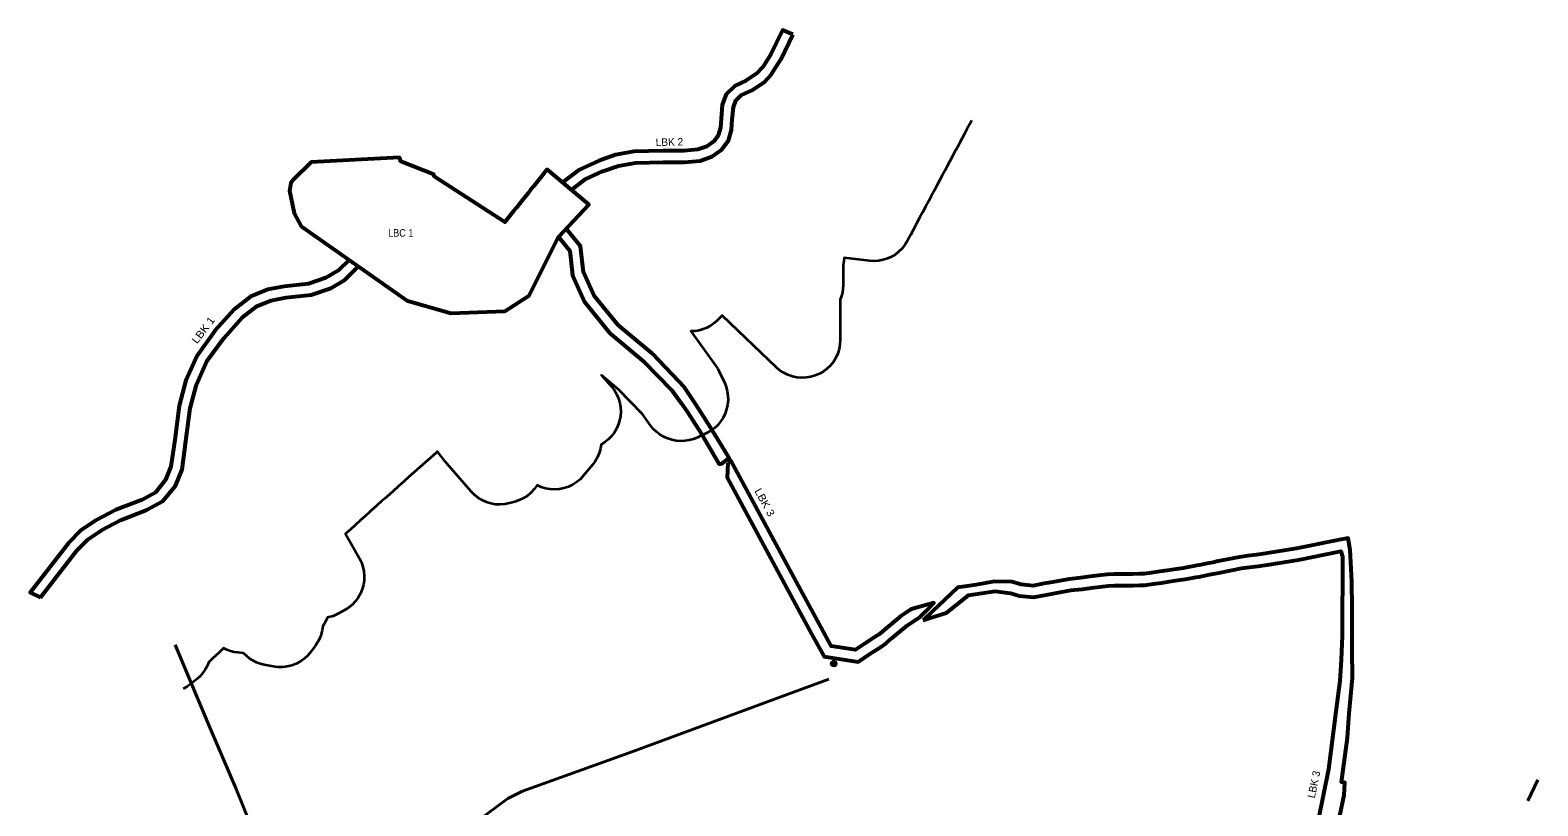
# Model space of a CAD drawing. Extents: x -555426 to -553015, y -1186745 to -1182687.
# Drawn here: x -555288 to -553293, y -1183714 to -1182687 of the extents above; entities that cross this region are included whole.
import ezdxf
from ezdxf.enums import TextEntityAlignment as Align

# ---------------------------------------------------------------- set-up
doc = ezdxf.new("R2010")
doc.units = 0
doc.header["$LTSCALE"] = 4
for name, color, linetype, lineweight in [('12', 7, 'Continuous', 53), ('14', 7, 'Continuous', 53), ('50', 7, 'Continuous', 35), ('51', 7, 'Continuous', 40), ('7', 7, 'Continuous', 35)]:
    doc.layers.add(name, color=color, linetype=linetype, lineweight=lineweight)
doc.layers.add('13', color=7, linetype='Continuous')

msp = doc.modelspace()

# ---------------------------------------------------------------- hatches: boundary and pattern name
at = {"layer": '50'}
msp.add_hatch(color=256, dxfattribs=at).paths.add_polyline_path([(-554222.657, -1183525.485, 1), (-554226.956, -1183525.485, 1)])

# ---------------------------------------------------------------- linework, layer by layer
at = {"layer": '12'}
for points in [[(-554278.839, -1182692.52), (-554292.751, -1182686.823), (-554308.218, -1182718.407), (-554319.193, -1182736.187), (-554326.623, -1182744.22), (-554340.883, -1182753.585), (-554355.867, -1182760.594), (-554367.234, -1182771.676), (-554372.315, -1182785.509), (-554374.031, -1182803.892), (-554374.904, -1182816.334), (-554377.789, -1182826.145), (-554383.471, -1182834.21), (-554392.863, -1182840.727), (-554404.898, -1182844.939), (-554423.272, -1182846.668), (-554450.709, -1182846.668), (-554488.789, -1182847.373), (-554513.544, -1182851.742), (-554535.945, -1182859.69), (-554561.973, -1182871.74), (-554583.662, -1182888.49)], [(-554571.889, -1182898.351), (-554554.141, -1182884.644), (-554530.273, -1182873.594), (-554509.706, -1182866.296), (-554487.337, -1182862.349), (-554450.571, -1182861.668), (-554422.568, -1182861.668), (-554401.67, -1182859.701), (-554385.985, -1182854.211), (-554372.739, -1182845.02), (-554364.099, -1182832.757), (-554360.054, -1182819.006), (-554359.079, -1182805.114), (-554357.561, -1182788.847), (-554354.326, -1182780.042), (-554347.213, -1182773.106), (-554333.551, -1182766.715), (-554316.857, -1182755.752), (-554307.193, -1182745.305), (-554295.068, -1182725.663), (-554278.839, -1182692.52)], [(-554373.37, -1183261.05), (-554363.18, -1183253.13), (-554387.431, -1183213.215), (-554406.75, -1183182.832), (-554421.72, -1183160.34), (-554465.312, -1183114.688), (-554510.264, -1183077.441), (-554542.023, -1183038.398), (-554556.094, -1183007.245), (-554559.906, -1182972.999), (-554577.646, -1182951.011)], [(-554589.32, -1182960.43), (-554574.33, -1182979.01), (-554570.74, -1183011.26), (-554554.89, -1183046.35), (-554520.97, -1183088.05), (-554475.52, -1183125.71), (-554439.49, -1183162.97), (-554426.66, -1183180.83), (-554419.18, -1183191.24), (-554400.25, -1183221.01), (-554377.12, -1183260.83), (-554373.37, -1183261.05)], [(-554866.158, -1182990.719), (-554881.217, -1183005.495), (-554896.861, -1183014.795), (-554919.81, -1183022.589), (-554952.084, -1183025.999), (-554973.942, -1183030.127), (-554996.146, -1183039.358), (-555018.025, -1183056.321), (-555043.915, -1183085.06), (-555067.478, -1183117.431), (-555082.368, -1183150.814), (-555091.194, -1183184.207), (-555097.029, -1183229.007), (-555101.98, -1183264.569), (-555109.072, -1183282.298), (-555122.428, -1183298.735), (-555140.345, -1183308.431), (-555175.164, -1183322.037), (-555200.858, -1183335.359), (-555221.24, -1183349.19), (-555237.778, -1183365.971), (-555288.383, -1183431.18), (-555274.545, -1183437.814)], [(-555274.545, -1183437.814), (-555226.472, -1183375.869), (-555211.594, -1183360.772), (-555193.168, -1183348.269), (-555168.964, -1183335.719), (-555134.021, -1183322.065), (-555112.666, -1183310.509), (-555095.992, -1183289.986), (-555087.376, -1183268.445), (-555082.163, -1183231.011), (-555076.444, -1183187.105), (-555068.176, -1183155.818), (-555054.422, -1183124.983), (-555032.247, -1183094.52), (-555007.777, -1183067.355), (-554988.538, -1183052.44), (-554969.624, -1183044.577), (-554949.9, -1183040.851), (-554916.57, -1183037.331), (-554890.547, -1183028.493), (-554872.001, -1183017.465), (-554853.67, -1182999.481)], [(-554110.58, -1183463.31), (-554103.48, -1183456.27), (-554092.27, -1183445.06), (-554122.231, -1183453.201), (-554124.207, -1183454.614), (-554136.184, -1183462.634), (-554157.583, -1183480.555), (-554164.408, -1183486.48), (-554171.218, -1183490.925), (-554184.025, -1183499.312), (-554196.042, -1183507.394), (-554228.053, -1183502.414), (-554240.95, -1183478.721), (-554274.264, -1183417.699), (-554310.485, -1183350.454), (-554361.077, -1183256.605), (-554365.04, -1183259.86)], [(-554365.04, -1183259.86), (-554366.04, -1183279.01), (-554323.69, -1183357.57), (-554287.45, -1183424.85), (-554254.12, -1183485.9), (-554237.684, -1183516.096), (-554192.544, -1183523.119), (-554175.73, -1183511.81), (-554163.01, -1183503.48), (-554155.35, -1183498.48), (-554147.85, -1183491.97), (-554127.17, -1183474.65), (-554115.67, -1183466.95), (-554110.58, -1183463.31)], [(-553560.8, -1183754.18), (-553549.47, -1183699.63), (-553548.22, -1183682.87), (-553552.596, -1183682.503), (-553545.043, -1183623.517), (-553542.638, -1183591.193), (-553538.153, -1183544.346), (-553538.853, -1183507.002), (-553538.59, -1183491.209), (-553538.57, -1183472.914), (-553538.638, -1183452.234), (-553539.179, -1183416.532), (-553541.455, -1183374.786), (-553543.938, -1183359.474), (-553557.65, -1183362.2), (-553612.39, -1183373.1), (-553653.56, -1183379.74), (-553665.24, -1183381.36), (-553676.67, -1183382.9), (-553687.79, -1183384.46), (-553718.16, -1183390.43), (-553722.99, -1183391.53), (-553728.14, -1183392.45), (-553732.81, -1183393.34), (-553738.51, -1183394.57), (-553744.23, -1183395.71), (-553748.21, -1183396.36), (-553752.95, -1183397.28), (-553757.56, -1183398.09), (-553762.06, -1183398.94), (-553771.65, -1183400.34), (-553782.96, -1183402.01), (-553793.28, -1183403.54), (-553804.29, -1183405.2), (-553814.16, -1183406.62), (-553820.26, -1183406.69), (-553829.02, -1183406.87), (-553837.21, -1183407), (-553845.49, -1183407.06), (-553853.98, -1183407.2), (-553862.46, -1183407.33), (-553870.96, -1183408.4), (-553885.46, -1183410.23), (-553897.94, -1183411.82), (-553913.31, -1183413.52), (-553934.77, -1183417.42), (-553946.22, -1183419.56), (-553961.04, -1183422.25), (-553976.68, -1183420.7), (-553988.73, -1183417.33), (-554011.96, -1183416.74), (-554036.25, -1183421.25), (-554048.21, -1183422.95), (-554061.25, -1183424.79), (-554078.44, -1183441.14), (-554094.02, -1183455.82), (-554106.58, -1183467.73)], [(-554106.58, -1183467.73), (-554075.726, -1183458.421), (-554046.426, -1183434.944), (-554011.182, -1183429.704), (-553990.975, -1183432.278), (-553979.461, -1183435.498), (-553960.428, -1183437.384), (-553943.503, -1183434.312), (-553932.051, -1183432.172), (-553911.142, -1183428.372), (-553896.168, -1183426.715), (-553883.573, -1183425.111), (-553869.084, -1183423.282), (-553861.405, -1183422.316), (-553853.741, -1183422.198), (-553845.312, -1183422.059), (-553837.037, -1183421.999), (-553828.747, -1183421.868), (-553820.02, -1183421.688), (-553813.001, -1183421.608), (-553802.104, -1183420.04), (-553791.062, -1183418.375), (-553780.765, -1183416.848), (-553769.471, -1183415.181), (-553759.583, -1183413.737), (-553754.87, -1183412.847), (-553750.223, -1183412.031), (-553745.572, -1183411.128), (-553741.554, -1183410.472), (-553735.462, -1183409.258), (-553729.823, -1183408.041), (-553725.417, -1183407.201), (-553720.004, -1183406.234), (-553715.047, -1183405.105), (-553685.3, -1183399.258), (-553674.627, -1183397.76), (-553663.208, -1183396.222), (-553651.335, -1183394.575), (-553609.73, -1183387.865), (-553553.598, -1183376.687), (-553551.63, -1183383.72), (-553552.01, -1183488.29), (-553553.42, -1183520.28), (-553554.96, -1183548.08), (-553560.51, -1183589.02), (-553570.03, -1183665.12), (-553583.88, -1183732.87)]]:
    msp.add_lwpolyline(points, dxfattribs=at)
at = {"layer": '14'}
msp.add_lwpolyline([(-554929.743, -1182946.105), (-554788.831, -1183044.975), (-554731.543, -1183061.607), (-554659.932, -1183058.835), (-554628.053, -1183038.044), (-554591, -1182963.93), (-554589.32, -1182960.43), (-554548.935, -1182917.576), (-554604.33, -1182871.18), (-554607.57, -1182875.37), (-554611.33, -1182880.08), (-554615.1, -1182884.8), (-554618.76, -1182889.39), (-554622.34, -1182893.87), (-554625.97, -1182898.29), (-554629.38, -1182902.63), (-554633.35, -1182907.44), (-554637.08, -1182912.33), (-554640.7, -1182916.69), (-554644.85, -1182921.99), (-554648.51, -1182926.36), (-554652.29, -1182931.05), (-554660.11, -1182940.98), (-554753.5, -1182880.52), (-554754.24, -1182878), (-554797.61, -1182860.51), (-554799.43, -1182855.5), (-554916.24, -1182861.73), (-554940.94, -1182885.43), (-554943.35, -1182888.88), (-554945.315, -1182899.449), (-554938.752, -1182929.243)], close=True, dxfattribs=at)
at = {"layer": '50'}
for radius in [3.332, 2.149]:
    msp.add_circle((-554224.806, -1183525.485), radius, dxfattribs=at)
at = {"layer": '51'}
msp.add_line((-553306.223, -1183706.964), (-553292.941, -1183679.475), dxfattribs=at)
for points in [[(-555096.259, -1183500.696), (-555050.637, -1183609.844), (-555016.334, -1183690.35), (-554989.423, -1183757.11), (-554981.106, -1183783.327), (-554976.024, -1183820.635), (-554968.516, -1183877.229), (-554966.438, -1183902.87), (-554901.757, -1183903.794), (-554892.286, -1183893.629), (-554839.155, -1183856.09), (-554793.88, -1183825.366), (-554760.962, -1183788.058), (-554748.083, -1183774.083)], [(-554722.904, -1183753.292), (-554656.144, -1183703.857), (-554636.97, -1183694.155), (-554490.514, -1183641.718), (-554303.17, -1183572.417), (-554231.271, -1183546.197)]]:
    msp.add_lwpolyline(points, dxfattribs=at)
at = {"layer": '7'}
for points in [[(-554042.529, -1182806.54), (-554045.307, -1182811.751), (-554048.608, -1182817.945), (-554051.847, -1182824.042), (-554055.031, -1182830.019), (-554058.369, -1182836.284), (-554061.654, -1182842.455), (-554064.862, -1182848.47), (-554068.062, -1182854.47), (-554071.245, -1182860.438), (-554074.618, -1182866.785), (-554077.993, -1182873.121), (-554081.352, -1182879.409), (-554084.784, -1182885.856), (-554088.415, -1182892.678), (-554092.103, -1182899.602), (-554095.816, -1182906.568), (-554099.521, -1182913.521), (-554103.242, -1182920.521), (-554107.3, -1182928.135), (-554111.209, -1182935.464), (-554115.164, -1182942.885), (-554119.262, -1182950.592), (-554123.347, -1182958.259), (-554127.513, -1182966.07), (-554130.633, -1182971.163), (-554134.339, -1182975.847), (-554138.576, -1182980.056), (-554143.285, -1182983.73), (-554148.399, -1182986.816), (-554153.844, -1182989.27), (-554159.543, -1182991.058), (-554165.415, -1182992.153), (-554171.375, -1182992.54), (-554177.339, -1182992.214), (-554211.103, -1182988.333), (-554211.616, -1182992.362), (-554212.217, -1182998.363), (-554212.212, -1183005.39), (-554212.332, -1183015.038), (-554212.381, -1183024.344), (-554212.63, -1183029.193), (-554213.38, -1183033.99), (-554214.624, -1183038.683), (-554216.347, -1183043.222)], [(-554216.347, -1183043.222), (-554216.32, -1183061.355), (-554216.18, -1183097.022), (-554216.546, -1183103.155), (-554217.66, -1183109.197), (-554219.508, -1183115.057), (-554222.06, -1183120.645), (-554225.278, -1183125.879), (-554229.114, -1183130.678), (-554233.51, -1183134.971), (-554238.398, -1183138.692), (-554243.707, -1183141.785), (-554249.354, -1183144.204), (-554255.256, -1183145.913), (-554261.323, -1183146.884), (-554267.462, -1183147.104), (-554273.583, -1183146.569), (-554279.592, -1183145.288), (-554285.398, -1183143.28), (-554290.914, -1183140.574), (-554296.057, -1183137.213), (-554300.748, -1183133.246), (-554351.34, -1183084.834), (-554372.353, -1183064.723), (-554379.064, -1183071.27), (-554383.237, -1183074.913), (-554387.788, -1183078.071), (-554392.66, -1183080.706), (-554397.795, -1183082.785), (-554403.128, -1183084.283), (-554408.594, -1183085.181), (-554414.126, -1183085.468), (-554381.247, -1183130.982), (-554378.419, -1183135.341), (-554376.643, -1183138.705), (-554369.573, -1183153.435), (-554367.294, -1183159.027), (-554365.705, -1183164.854), (-554364.83, -1183170.829), (-554364.682, -1183176.866), (-554365.263, -1183182.877), (-554366.565, -1183188.774), (-554368.567, -1183194.471), (-554371.242, -1183199.885), (-554374.551, -1183204.938), (-554378.444, -1183209.554), (-554382.865, -1183213.668), (-554387.75, -1183217.218), (-554393.028, -1183220.154), (-554405.038, -1183225.914), (-554410.413, -1183228.117), (-554416.008, -1183229.683), (-554421.746, -1183230.588), (-554427.551, -1183230.822), (-554433.343, -1183230.382), (-554439.046, -1183229.272), (-554444.581, -1183227.508), (-554449.874, -1183225.115), (-554454.854, -1183222.123), (-554459.454, -1183218.574), (-554463.61, -1183214.515), (-554467.268, -1183210.002), (-554477.97, -1183195.105), (-554509.545, -1183162.451), (-554532.143, -1183143.633), (-554518.631, -1183159.243), (-554515.073, -1183163.964), (-554512.097, -1183169.072), (-554509.748, -1183174.496), (-554508.056, -1183180.16), (-554507.046, -1183185.985), (-554506.733, -1183191.888), (-554507.12, -1183197.787), (-554508.203, -1183203.599), (-554509.965, -1183209.241), (-554512.382, -1183214.636), (-554515.421, -1183219.707), (-554519.039, -1183224.382), (-554523.184, -1183228.597), (-554527.799, -1183232.292), (-554532.818, -1183235.414), (-554533.691, -1183241.174), (-554535.262, -1183246.784), (-554537.506, -1183252.16), (-554540.391, -1183257.221), (-554543.872, -1183261.892), (-554556.435, -1183277.021), (-554560.631, -1183281.483), (-554565.344, -1183285.395), (-554570.503, -1183288.696), (-554576.03, -1183291.337), (-554581.839, -1183293.277), (-554587.844, -1183294.487), (-554593.952, -1183294.947), (-554600.07, -1183294.652), (-554606.105, -1183293.606), (-554611.965, -1183291.825), (-554617.561, -1183289.335), (-554621.144, -1183294.456), (-554625.349, -1183299.079), (-554630.108, -1183303.13)], [(-554630.108, -1183303.13), (-554635.344, -1183306.542), (-554640.971, -1183309.26), (-554646.899, -1183311.241), (-554654.029, -1183313.161), (-554660.118, -1183314.4), (-554666.314, -1183314.875), (-554672.522, -1183314.578), (-554678.644, -1183313.513), (-554684.587, -1183311.697), (-554690.259, -1183309.157), (-554695.571, -1183305.934), (-554700.443, -1183302.077), (-554704.799, -1183297.644), (-554736.939, -1183260.594), (-554739.184, -1183257.811), (-554749.11, -1183244.563), (-554751.224, -1183246.463), (-554758.608, -1183253.016), (-554765.643, -1183259.215), (-554772.609, -1183265.479), (-554779.925, -1183272.041), (-554787.13, -1183278.372), (-554794.075, -1183284.625), (-554801.254, -1183291.06), (-554808.527, -1183297.581), (-554815.988, -1183304.186), (-554819.57, -1183307.298), (-554822.737, -1183310.117), (-554829.881, -1183316.589), (-554836.845, -1183322.79), (-554840.492, -1183326.144), (-554843.546, -1183328.959), (-554844.409, -1183329.736), (-554851.577, -1183336.044), (-554858.225, -1183341.946), (-554864.933, -1183348.163), (-554866.091, -1183349.204), (-554871.107, -1183353.57), (-554862.775, -1183368.352), (-554852.707, -1183386.106), (-554850.05, -1183391.53), (-554848.067, -1183397.236), (-554846.786, -1183403.138), (-554846.226, -1183409.153), (-554846.396, -1183415.19), (-554847.292, -1183421.164), (-554848.902, -1183426.985), (-554851.203, -1183432.57), (-554854.16, -1183437.837), (-554857.731, -1183442.709), (-554861.863, -1183447.114), (-554866.496, -1183450.989), (-554871.563, -1183454.277), (-554880.337, -1183459.153), (-554887.509, -1183462.425), (-554895.013, -1183464.436), (-554898.639, -1183472.211), (-554901.2, -1183475.868), (-554901.87, -1183481.339), (-554903.17, -1183486.695), (-554905.081, -1183491.865), (-554907.578, -1183496.778), (-554910.628, -1183501.369), (-554916.958, -1183509.929), (-554920.999, -1183514.731), (-554925.61, -1183518.989), (-554930.718, -1183522.636), (-554936.242, -1183525.615), (-554942.097, -1183527.877), (-554948.188, -1183529.389), (-554954.421, -1183530.125), (-554960.697, -1183530.075), (-554966.918, -1183529.239), (-554978.778, -1183526.879), (-554983.909, -1183525.59), (-554988.87, -1183523.75), (-554993.602, -1183521.383), (-554998.048, -1183518.516), (-555002.157, -1183515.183), (-555005.879, -1183511.423), (-555013.388, -1183510.752), (-555018.322, -1183510.063), (-555023.166, -1183508.9), (-555027.875, -1183507.273), (-555032.404, -1183505.197), (-555035.924, -1183508.403), (-555039.218, -1183511.498), (-555046.403, -1183518.17), (-555051.906, -1183523.608), (-555053.963, -1183528.636), (-555056.562, -1183533.406), (-555059.672, -1183537.861), (-555063.255, -1183541.945), (-555067.266, -1183545.609), (-555076.09, -1183552.726), (-555081.111, -1183556.284), (-555085.651, -1183558.726)]]:
    msp.add_lwpolyline(points, dxfattribs=at)

# ---------------------------------------------------------------- texts
at = {"layer": '13'}
for s, rotation, p in [('LBK 2', 1.489, (-554442.159, -1182839.876)), ('LBK 3', 78.305, (-553584.489, -1183686.383))]:
    msp.add_text(s, height=10, rotation=rotation, dxfattribs=at).set_placement(p, align=Align.CENTER)
at = {"layer": '13', "width": 0.9}
msp.add_text('LBC 1', height=10, dxfattribs=at).set_placement((-554797.917, -1182960.276), align=Align.CENTER)
at = {"layer": '13', "width": 1.1}
for s, rotation, p in [('LBK 1', 52.768, (-555055.332, -1183086.952)), ('LBK 3', 298.687, (-554320.643, -1183314.376))]:
    msp.add_text(s, height=10, rotation=rotation, dxfattribs=at).set_placement(p, align=Align.CENTER)

doc.saveas('drawing.dxf')
